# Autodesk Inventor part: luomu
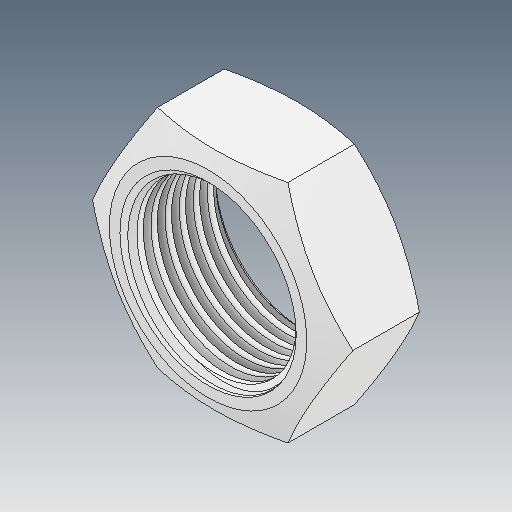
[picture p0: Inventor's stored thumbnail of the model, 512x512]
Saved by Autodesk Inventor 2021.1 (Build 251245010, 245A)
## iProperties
Created: 2021-05
Part Number: luomu
Material: Ogólny
Document SubType Name: Modeling
Designer: user
Density: 1 g/cm^3
Appearance: Domyślna
Author: user
Revision Number: ÈÎºÎ
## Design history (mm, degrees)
feature "ÊäÈë1"
node "Bryła1"
